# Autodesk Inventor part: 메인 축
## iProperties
Company: 한국ATC센터
Created: 2014-07
Part Number: 메인 축
Document SubType Name: 모델링
Designer: KYOUNG IL JANG
Mass: 21.4462 g
Surface Area: 72.5109 cm^2
Volume: 21.4462 cm^3
Density: 1 g/cm^3
변환 표준: STEP AP214IS
파일 이름: C:\Users\SeoGD\Desktop\?쒗뿕\硫붿씤 異?.stp
전처리기: Build: 253, Release: 2010 SP1 - Date: Wed 07/29/2009
전송 단위: 밀리미터
불확실성: 0.01
Author: KYOUNG IL JANG
